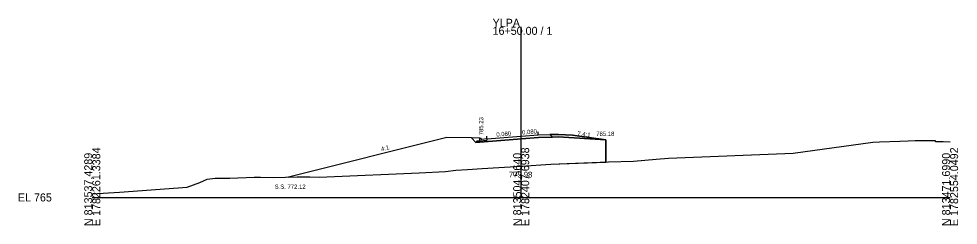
# Model space of a CAD drawing. Extents: x -76 to 1303, y -10 to 9544.
# Drawn here: x -25.7 to 302.8, y 6490.3 to 6562.4 of the extents above; entities that cross this region are included whole.
import ezdxf

# ---------------------------------------------------------------- set-up
doc = ezdxf.new("R2010")
doc.units = 0
for name, color, linetype in [('Exist Cross Section Cell', 7, 'Continuous'), ('Exist XS Center Line Elevation Label', 7, 'Continuous'), ('Exist XS Ground Line', 7, 'Continuous'), ('Prop XS Ditch Standard Text', 7, 'Continuous'), ('Prop XS Dump Level', 7, 'Continuous'), ('Prop XS Earthwork Shape', 7, 'Continuous'), ('Prop XS EOT Tick Mark', 7, 'Continuous'), ('Prop XS Finish Grade', 7, 'Continuous'), ('Prop XS Finish Grade CurbGutter', 7, 'Continuous'), ('Prop XS Finish Grade Earthwork', 7, 'Continuous'), ('Prop XS Finish Grade Paved Shoulder', 7, 'Continuous'), ('Prop XS Finish Grade Pavement', 7, 'Continuous'), ('Prop XS Hydro Elevations', 7, 'Continuous'), ('Prop XS Pvmt Edge Slope', 7, 'Continuous'), ('Prop XS SE Text', 7, 'Continuous'), ('Prop XS Side Slope Text', 7, 'Continuous'), ('Prop XS SS Elevation Text', 7, 'Continuous'), ('Prop XS Subgrade CurbGutter', 7, 'Continuous'), ('Prop XS Subgrade Earthwork', 7, 'Continuous'), ('Scratch_Level_1', 7, 'Continuous'), ('Scratch_Level_3', 7, 'Continuous')]:
    doc.layers.add(name, color=color, linetype=linetype)

msp = doc.modelspace()

# ---------------------------------------------------------------- linework, layer by layer
at = {"layer": 'Exist Cross Section Cell'}
for p, q in [((150, 6500), (150, 6559.62)), ((0, 6500), (150, 6500)), ((150, 6500), (300, 6500))]:
    msp.add_line(p, q, dxfattribs=at)
at = {"layer": 'Exist XS Ground Line'}
for p, q in [((245.1, 6515.44), (272.94, 6519.33)), ((272.94, 6519.33), (275.3, 6519.44)), ((275.3, 6519.44), (282.45, 6519.72)), ((282.45, 6519.72), (285.34, 6519.83)), ((285.34, 6519.83), (287.81, 6519.85)), ((287.81, 6519.85), (294.66, 6519.87)), ((294.66, 6519.87), (294.85, 6519.58)), ((294.85, 6519.58), (297.55, 6519.53)), ((297.55, 6519.53), (300, 6519.47)), ((201.53, 6513.73), (245.1, 6515.44)), ((150, 6510.98), (160.35, 6511.62)), ((160.35, 6511.62), (180.51, 6512.41)), ((180.51, 6512.41), (189.23, 6512.73)), ((189.23, 6512.73), (197.2, 6513.37)), ((197.2, 6513.37), (201.53, 6513.73)), ((81.99, 6507.22), (114.28, 6508.63)), ((114.28, 6508.63), (123.5, 6509.1)), ((123.5, 6509.1), (127.18, 6509.55)), ((127.18, 6509.55), (131.27, 6509.81)), ((131.27, 6509.81), (136.32, 6510.13)), ((136.32, 6510.13), (150, 6510.98)), ((33.2, 6503.54), (37.59, 6505.24)), ((37.59, 6505.24), (40.14, 6506.42)), ((40.14, 6506.42), (42.94, 6506.73)), ((42.94, 6506.73), (44.7, 6506.76)), ((44.7, 6506.76), (46.99, 6506.77)), ((46.99, 6506.77), (48.09, 6506.78)), ((48.09, 6506.78), (56.58, 6507.1)), ((56.58, 6507.1), (58.83, 6507.09)), ((58.83, 6507.09), (63.54, 6507.01)), ((63.54, 6507.01), (71.63, 6507.18)), ((71.63, 6507.18), (76.04, 6507.15)), ((76.04, 6507.15), (79.38, 6507.13)), ((79.38, 6507.13), (81.99, 6507.22)), ((0, 6501.23), (9.58, 6501.9)), ((9.58, 6501.9), (33.2, 6503.54))]:
    msp.add_line(p, q, dxfattribs=at)
at = {"layer": 'Prop XS Dump Level'}
for p, q in [((138, 6520.47), (150, 6521.43)), ((150, 6521.43), (156, 6521.91))]:
    msp.add_line(p, q, dxfattribs=at)
at = {"layer": 'Prop XS Earthwork Shape'}
msp.add_lwpolyline([(136.32, 6510.13), (150, 6510.98), (160.35, 6511.62), (179.66, 6512.37), (179.66, 6520.18), (162.98, 6521.14), (160.9, 6521.09), (156.05, 6521), (150.07, 6520.52), (134.16, 6519.25), (132.61, 6520.79), (124, 6520.97), (68.58, 6507.12), (71.63, 6507.18), (76.04, 6507.15), (79.38, 6507.13), (81.99, 6507.22), (114.28, 6508.63), (123.5, 6509.1), (127.18, 6509.55), (131.27, 6509.81)], close=True, dxfattribs=at)
at = {"layer": 'Prop XS EOT Tick Mark'}
for p, q in [((138, 6520.47), (138, 6521.47)), ((156, 6521.91), (156, 6522.91))]:
    msp.add_line(p, q, dxfattribs=at)
at = {"layer": 'Prop XS Finish Grade'}
for p, q in [((160, 6521.99), (163, 6522.05)), ((163, 6522.05), (168, 6521.75)), ((168, 6521.75), (179.66, 6520.18)), ((135.5, 6520.73), (132.61, 6520.79))]:
    msp.add_line(p, q, dxfattribs=at)
at = {"layer": 'Prop XS Finish Grade CurbGutter'}
for p, q in [((135.5, 6520.73), (135.75, 6520.73)), ((135.75, 6520.73), (135.88, 6520.72)), ((135.97, 6520.63), (135.88, 6520.72)), ((136.03, 6520.38), (135.97, 6520.63)), ((136.13, 6520.29), (136.03, 6520.38)), ((136.25, 6520.26), (136.13, 6520.29)), ((138, 6520.47), (136.25, 6520.26))]:
    msp.add_line(p, q, dxfattribs=at)
at = {"layer": 'Prop XS Finish Grade Earthwork'}
for p, q in [((124, 6520.97), (68.58, 6507.12)), ((132.61, 6520.79), (124, 6520.97)), ((179.66, 6520.18), (179.66, 6512.37))]:
    msp.add_line(p, q, dxfattribs=at)
at = {"layer": 'Prop XS Finish Grade Paved Shoulder'}
msp.add_line((156, 6521.91), (160, 6521.99), dxfattribs=at)
at = {"layer": 'Prop XS Finish Grade Pavement'}
for p, q in [((138, 6520.47), (150, 6521.43)), ((150, 6521.43), (156, 6521.91))]:
    msp.add_line(p, q, dxfattribs=at)
at = {"layer": 'Prop XS Pvmt Edge Slope'}
for p, q in [((160, 6521.99), (160.9, 6521.09)), ((134.5, 6519.61), (134.16, 6519.25)), ((135.5, 6519.69), (134.5, 6519.61))]:
    msp.add_line(p, q, dxfattribs=at)
at = {"layer": 'Prop XS Subgrade CurbGutter'}
for p, q in [((135.5, 6519.69), (135.5, 6520.73)), ((138, 6519.89), (135.5, 6519.69)), ((138, 6520.47), (138, 6519.89))]:
    msp.add_line(p, q, dxfattribs=at)
at = {"layer": 'Prop XS Subgrade Earthwork'}
for p, q in [((134.16, 6519.25), (132.61, 6520.79)), ((134.16, 6519.25), (150.07, 6520.52)), ((150.07, 6520.52), (156.05, 6521)), ((156.05, 6521), (160.9, 6521.09)), ((160.9, 6521.09), (162.98, 6521.14)), ((162.98, 6521.14), (179.66, 6520.18))]:
    msp.add_line(p, q, dxfattribs=at)
at = {"layer": 'Scratch_Level_1'}
msp.add_line((179.66, 6520.18), (179.66, 6512.37), dxfattribs=at)
at = {"layer": 'Scratch_Level_3'}
for p, q in [((163, 6522.05), (160, 6521.99)), ((160, 6521.99), (160.9, 6521.09)), ((168, 6521.75), (163, 6522.05)), ((179.66, 6520.18), (168, 6521.75)), ((160.9, 6521.09), (162.98, 6521.14)), ((162.98, 6521.14), (179.66, 6520.18))]:
    msp.add_line(p, q, dxfattribs=at)

# ---------------------------------------------------------------- texts
at = {"layer": 'Exist Cross Section Cell'}
for s, p in [('YLPA', (140, 6559.62)), ('16+50.00 / 1', (140, 6556.82)), ('EL 765', (-26, 6498.6))]:
    msp.add_text(s, height=2.8, dxfattribs=at).set_placement(p)
for s, p in [('N 813537.4289', (0, 6490)), ('E 1782261.3384', (2.8, 6490)), ('N 813504.5640', (150, 6490)), ('E 1782407.6938', (152.8, 6490)), ('N 813471.6990', (300, 6490)), ('E 1782554.0492', (302.8, 6490))]:
    msp.add_text(s, height=2.8, rotation=90, dxfattribs=at).set_placement(p)
at = {"layer": 'Exist XS Center Line Elevation Label'}
msp.add_text('775.98', height=2, dxfattribs=at).set_placement((145.73, 6506.98))
at = {"layer": 'Prop XS Ditch Standard Text'}
msp.add_text('785.18', height=1.5, dxfattribs=at).set_placement((176.26, 6521.49))
at = {"layer": 'Prop XS Dump Level'}
msp.add_text('Case4', height=0.04, dxfattribs=at).set_placement((168, 6521.71))
at = {"layer": 'Prop XS Hydro Elevations'}
msp.add_text('785.23', height=1.5, rotation=90, dxfattribs=at).set_placement((136.75, 6521.73))
at = {"layer": 'Prop XS SE Text'}
for p in [(141.38, 6521.24), (150.38, 6521.96)]:
    msp.add_text('0.080', height=1.5, rotation=4.5739, dxfattribs=at).set_placement(p)
at = {"layer": 'Prop XS Side Slope Text'}
for s, rotation, p in [('7.4:1', 351.6566, (169.59, 6521.73)), ('4:1', 16.2171, (101.22, 6516.08))]:
    msp.add_text(s, height=1.5, rotation=rotation, dxfattribs=at).set_placement(p)
at = {"layer": 'Prop XS SS Elevation Text'}
msp.add_text('S.S. 772.12', height=1.5, dxfattribs=at).set_placement((63.8, 6503.01))

doc.saveas('drawing.dxf')
